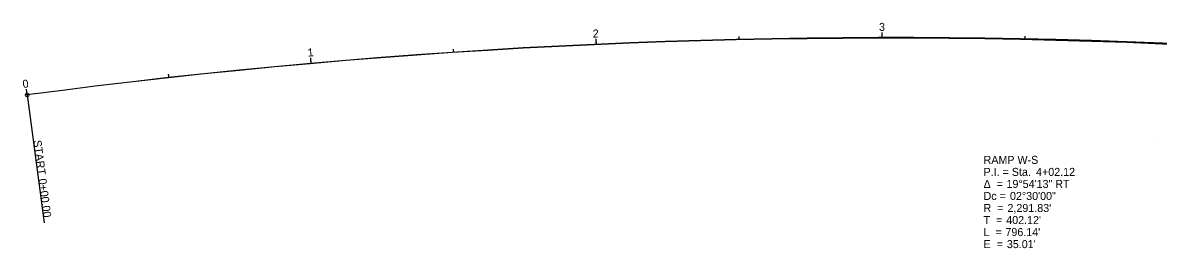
# Model space of a CAD drawing. Extents: x 2196792 to 2197586, y 661568 to 661670.
# Drawn here: x 2196792.1 to 2197189.4, y 661591.6 to 661670.3 of the extents above; entities that cross this region are included whole.
import ezdxf

# ---------------------------------------------------------------- set-up
doc = ezdxf.new("R2010")
doc.units = 0
for name, color, linetype in [('Default', 7, 'Continuous'), ('GE_X_Alignment', 7, 'Continuous'), ('GE_X_Alignment_1000_Stations', 7, 'Continuous'), ('GE_X_Alignment_100_Curve_Data', 7, 'Continuous'), ('GE_X_Alignment_100_Stations', 7, 'Continuous'), ('GE_X_Alignment_500_Stations', 7, 'Continuous'), ('SC_Scratch2', 7, 'Continuous')]:
    doc.layers.add(name, color=color, linetype=linetype)

msp = doc.modelspace()

# ---------------------------------------------------------------- linework, layer by layer
at = {"layer": 'Default'}
for centre in [(2196992.8, 661662.62), (2197092.77, 661664.87), (2196893.03, 661656.02), (2196793.64, 661645.07), (2196793.64, 661645.07), (2196793.64, 661645.07), (2196793.64, 661645.07), (2196793.64, 661645.07), (2196793.64, 661645.07), (2197189.36, 661628.39), (2197189.36, 661628.39), (2197189.36, 661628.39)]:
    msp.add_circle(centre, 0.0000833, dxfattribs=at)
at = {"layer": 'GE_X_Alignment'}
msp.add_arc((2197094.29, 659373.04), 2291.83, 77.6346, 97.53811, dxfattribs=at)
at = {"layer": 'GE_X_Alignment_1000_Stations'}
for q in [(2196793.37, 661647.05), (2196799.54, 661600.45)]:
    msp.add_line((2196793.64, 661645.07), q, dxfattribs=at)
msp.add_circle((2196793.64, 661645.07), 0.6, dxfattribs=at)
at = {"layer": 'GE_X_Alignment_100_Stations'}
for p, q in [((2197092.77, 661664.87), (2197092.77, 661666.87)), ((2196992.8, 661662.62), (2196992.71, 661664.62)), ((2197042.77, 661664.29), (2197042.75, 661665.49)), ((2197142.76, 661664.36), (2197142.79, 661665.56)), ((2196942.88, 661659.86), (2196942.8, 661661.06)), ((2196893.03, 661656.02), (2196892.85, 661658.01)), ((2196843.27, 661651.08), (2196843.14, 661652.28)), ((2196793.64, 661645.07), (2196793.37, 661647.05)), ((2196793.64, 661645.07), (2196799.54, 661600.45))]:
    msp.add_line(p, q, dxfattribs=at)
msp.add_circle((2196793.64, 661645.07), 0.6, dxfattribs=at)
at = {"layer": 'GE_X_Alignment_500_Stations'}
for p, q in [((2196992.8, 661662.62), (2196992.75, 661663.82)), ((2197092.77, 661664.87), (2197092.77, 661666.07)), ((2196893.03, 661656.02), (2196892.92, 661657.21)), ((2196793.64, 661645.07), (2196793.37, 661647.05)), ((2196793.64, 661645.07), (2196799.54, 661600.45))]:
    msp.add_line(p, q, dxfattribs=at)
msp.add_circle((2196793.64, 661645.07), 0.6, dxfattribs=at)
at = {"layer": 'SC_Scratch2'}
msp.add_arc((2197095.93, 659373.26), 2291.83, 77.6734, 97.57937, dxfattribs=at)

# ---------------------------------------------------------------- texts
at = {"layer": 'GE_X_Alignment_1000_Stations'}
for s, rotation, p in [('0', 7.5381, (2196792.21, 661647.45)), ('START', 277.5381, (2196795.79, 661629.13)), ('0+00.00', 277.5381, (2196797.57, 661615.69))]:
    msp.add_text(s, height=2.8, rotation=rotation, dxfattribs=at).set_placement(p)
at = {"layer": 'GE_X_Alignment_100_Curve_Data'}
for s, p in [('RAMP W-S', (2197128.27, 661621.02)), ('P.I. = Sta. ', (2197128.27, 661616.82)), ('4+02.12', (2197146.64, 661616.82)), ('Δ  = ', (2197128.27, 661612.62)), ('19°54\'13" RT', (2197136.29, 661612.62)), ('Dc = ', (2197128.27, 661608.42)), ('02°30\'00"', (2197137.51, 661608.42)), ('R  = ', (2197128.27, 661604.22)), ("2,291.83'", (2197136.64, 661604.22)), ('T  = ', (2197128.27, 661600.02)), ("402.12'", (2197136.2, 661600.02)), ('L  = ', (2197128.27, 661595.82)), ("796.14'", (2197135.92, 661595.82)), ('E  = ', (2197128.27, 661591.62)), ("35.01'", (2197136.42, 661591.62))]:
    msp.add_text(s, height=2.8, dxfattribs=at).set_placement(p)
at = {"layer": 'GE_X_Alignment_100_Stations'}
for s, rotation, p in [('3', 0.0381, (2197091.68, 661667.42)), ('2', 2.5381, (2196991.59, 661665.07)), ('1', 5.0381, (2196891.87, 661658.43)), ('0', 7.5381, (2196792.21, 661647.45)), ('START', 277.5381, (2196795.79, 661629.13)), ('0+00.00', 277.5381, (2196797.57, 661615.69))]:
    msp.add_text(s, height=2.8, rotation=rotation, dxfattribs=at).set_placement(p)
at = {"layer": 'GE_X_Alignment_500_Stations'}
for s, rotation, p in [('0', 7.5381, (2196792.21, 661647.45)), ('START', 277.5381, (2196795.79, 661629.13)), ('0+00.00', 277.5381, (2196797.57, 661615.69))]:
    msp.add_text(s, height=2.8, rotation=rotation, dxfattribs=at).set_placement(p)

doc.saveas('drawing.dxf')
